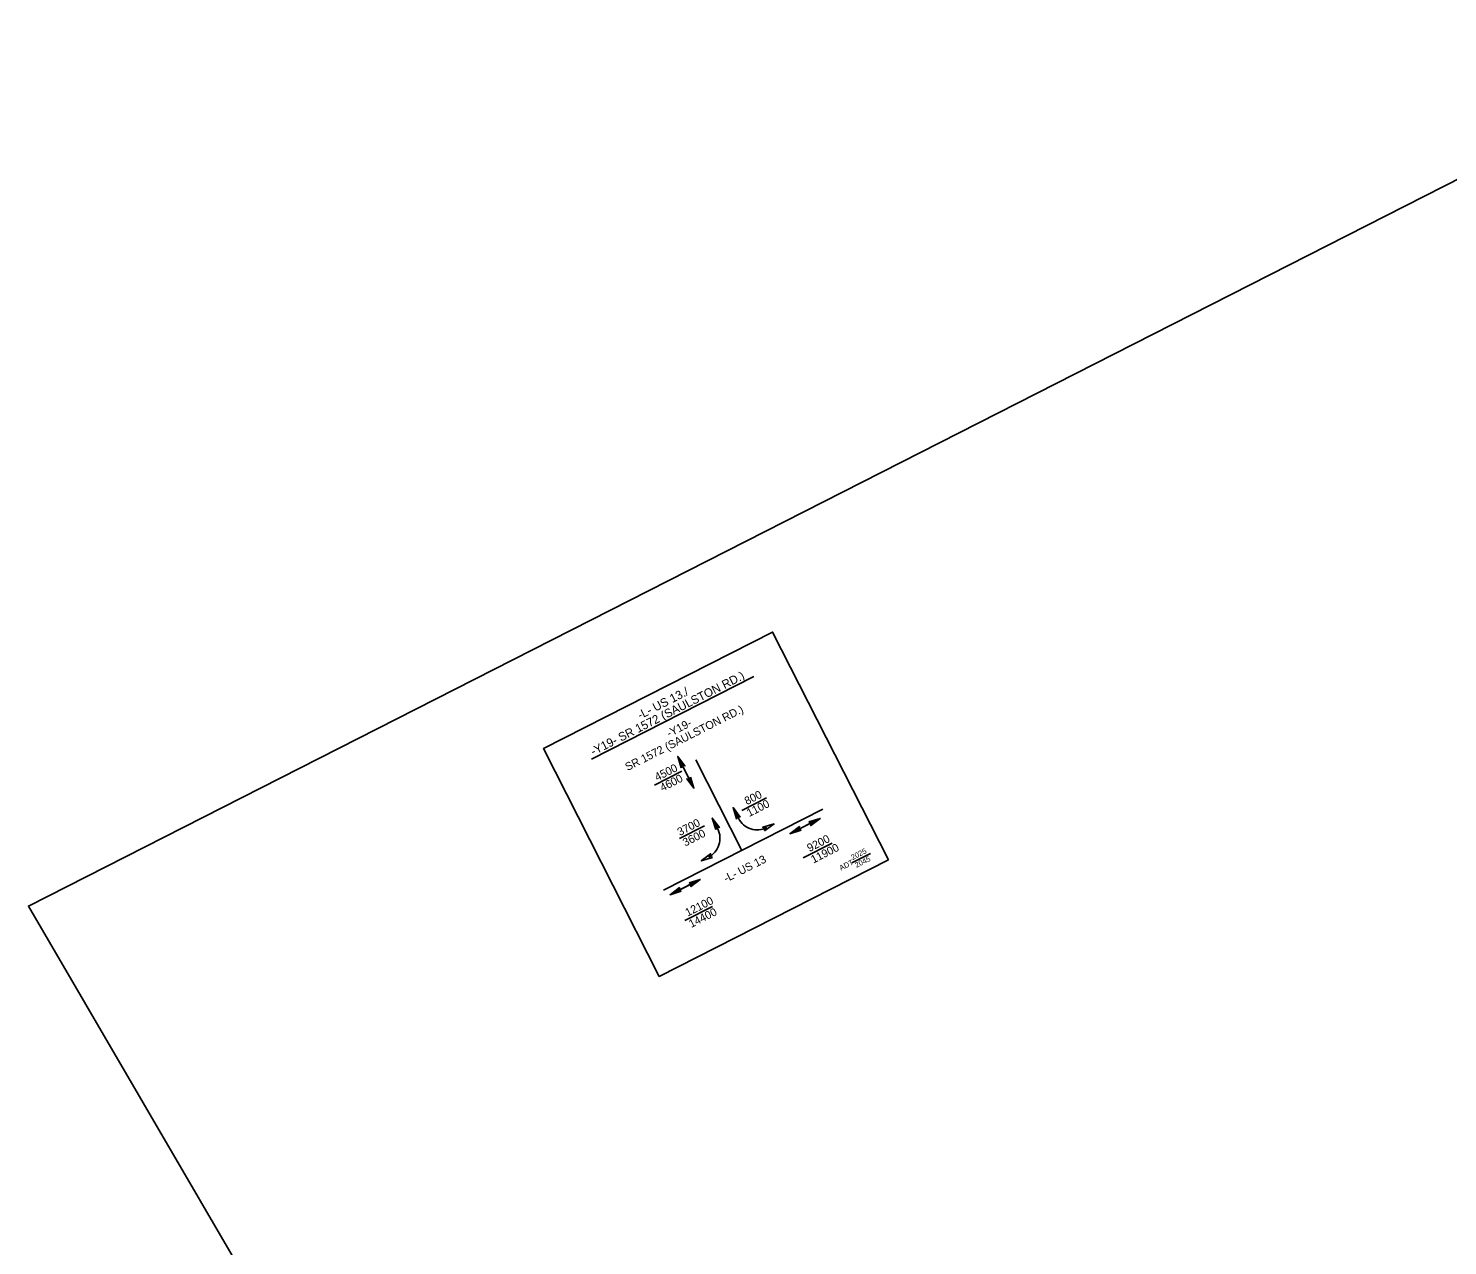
# Model space of a CAD drawing. Extents: x 2330830 to 2332603, y 611313 to 612915.
# Drawn here: x 2330830 to 2331716, y 612073 to 612833 of the extents above; entities that cross this region are included whole.
import ezdxf

# ---------------------------------------------------------------- set-up
doc = ezdxf.new("R2010")
doc.units = 0
for name, color, linetype in [('Prop AutoTurn Projected Path', 7, 'Continuous'), ('Scratch_Level_1', 7, 'Continuous'), ('Scratch_Level_6', 7, 'Continuous')]:
    doc.layers.add(name, color=color, linetype=linetype)

msp = doc.modelspace()

# ---------------------------------------------------------------- linework, layer by layer
at = {"layer": 'Prop AutoTurn Projected Path'}
msp.add_lwpolyline([(2331043.17, 611919.24), (2331331.4, 611606), (2331484.16, 611439.99), (2332475.1, 611946.91), (2332084.78, 612714.71), (2331991.86, 612667.61), (2331907.69, 612833.18), (2330829.74, 612285.17)], close=True, dxfattribs=at)
at = {"layer": 'Scratch_Level_1'}
msp.add_lwpolyline([(2331366.92, 612314), (2331294.59, 612456.28), (2331151.46, 612383.52), (2331223.78, 612241.24)], close=True, dxfattribs=at)
at = {"layer": 'Scratch_Level_6'}
for p, q in [((2331181.4, 612376.96), (2331282.83, 612428.52)), ((2331235.33, 612378.59), (2331242.07, 612365.33)), ((2331220.82, 612360.69), (2331237.82, 612369.34)), ((2331245.44, 612358.71), (2331238.7, 612371.96)), ((2331275.3, 612319.94), (2331246.55, 612376.49)), ((2331275.26, 612344.97), (2331290.8, 612352.88)), ((2331325.87, 612345.65), (2331226.47, 612295.11)), ((2331273.26, 612340), (2331269.87, 612346.69)), ((2331236.51, 612327.37), (2331252.03, 612335.27)), ((2331260.28, 612333.4), (2331256.88, 612340.09)), ((2331305.41, 612330.31), (2331318.66, 612337.07)), ((2331324.29, 612339.95), (2331311.05, 612333.19)), ((2331313.74, 612315.25), (2331331.77, 612324.42)), ((2331344, 612312.14), (2331355.61, 612318.04)), ((2331230.52, 612292.24), (2331243.76, 612299)), ((2331249.4, 612301.87), (2331236.15, 612295.12)), ((2331239.71, 612276.09), (2331257, 612284.89))]:
    msp.add_line(p, q, dxfattribs=at)
for points in [[(2331237.56, 612371.59), (2331235.33, 612378.59), (2331239.79, 612372.72), (2331238.2, 612372.95)], [(2331243.21, 612365.71), (2331245.44, 612358.71), (2331240.98, 612364.57), (2331242.57, 612364.35)], [(2331274.21, 612340.76), (2331269.87, 612346.69), (2331271.97, 612339.63), (2331272.73, 612341.05)], [(2331259.11, 612333.09), (2331256.88, 612340.09), (2331261.34, 612334.22), (2331259.75, 612334.45)], [(2331289.56, 612332.16), (2331295.49, 612336.5), (2331288.42, 612334.39), (2331289.84, 612333.63)], [(2331312.41, 612332.55), (2331305.41, 612330.31), (2331311.27, 612334.78), (2331311.05, 612333.19)], [(2331317.3, 612337.71), (2331324.29, 612339.95), (2331318.43, 612335.48), (2331318.66, 612337.07)], [(2331257.02, 612315.62), (2331250.02, 612313.38), (2331255.88, 612317.85), (2331255.66, 612316.26)], [(2331242.4, 612299.63), (2331249.4, 612301.87), (2331243.54, 612297.4), (2331243.76, 612299)], [(2331237.52, 612294.48), (2331230.52, 612292.24), (2331236.38, 612296.71), (2331236.15, 612295.12)]]:
    msp.add_lwpolyline(points, close=True, dxfattribs=at)
for centre, start, end in [((2331248.53, 612327.42), 296.97284, 26.97308), ((2331285.02, 612345.97), 206.91999, 296.92022)]:
    msp.add_arc(centre, 13.18, start, end, dxfattribs=at)

# ---------------------------------------------------------------- texts
for s, height, rotation, p in [('-Y19- SR 1572 (SAULSTON RD.)', 5.3333, 26.91071, (2331182.57, 612379.02)), ('-L- US 13./', 5.3333, 26.91071, (2331211.84, 612401.71)), ('SR 1572 (SAULSTON RD.)', 5, 26.91071, (2331203.99, 612369.46)), ('-Y19-', 5, 26.91071, (2331229.97, 612390.5)), ('4500', 5, 26.91071, (2331222.48, 612363.1)), ('4600', 5, 26.91071, (2331225.78, 612356.61)), ('800', 5, 26.91071, (2331278.52, 612348.17)), ('1100', 5, 26.91071, (2331279.95, 612340.74)), ('3700', 5, 26.91071, (2331236.61, 612328.88)), ('3600', 5, 26.91071, (2331239.96, 612322.28)), ('9200', 5, 26.91071, (2331317.62, 612318.87)), ('11900', 5, 26.91071, (2331320.03, 612311.71)), ('-L- US 13', 5, 26.91071, (2331265.58, 612299.86)), ('2025', 3.333, 26.9201, (2331344.54, 612313.85)), ('2045', 3.333, 26.9201, (2331346.96, 612308.98)), ('ADT', 3.333, 26.9201, (2331337.25, 612307.23)), ('12100', 5, 26.91071, (2331241.53, 612278.57)), ('14400', 5, 26.91071, (2331243.77, 612271.52))]:
    msp.add_text(s, height=height, rotation=rotation, dxfattribs=at).set_placement(p)

doc.saveas('drawing.dxf')
